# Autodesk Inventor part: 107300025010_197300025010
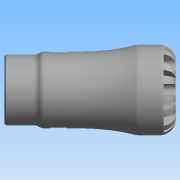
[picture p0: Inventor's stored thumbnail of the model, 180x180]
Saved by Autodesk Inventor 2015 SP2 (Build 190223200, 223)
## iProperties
Created: 2016-12
Part Number: 107300025010_197300025010
Material: Generic
Description: PLASSON FEMALE INTEGRAL BRASS THREAD 25X1" SERIES 1
Document SubType Name: Modeling
Designer: KIM
Density: 1 g/cm^3
Appearance: Default
Author: KIM
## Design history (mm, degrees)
derived "1073.ipt"
feature "Solid1::1073.ipt"
tag "TaggingFeature1"
body "Solid1"
other parameters: "d0" = 89, "d1" = 20.16, "d2" = 25, "d3" = 31.25, "d4" = 47, "d6" = 48, "d8" = 39.95, "d13" = 6.3, "d14" = 6.3, "d15" = 0, "d17" = 360 deg, "d19" = 8 deg, "d20" = 0.5, "d21" = 0.5, "d22" = 8 deg, "d24" = 0, "d26" = 360 deg, "d32" = 4.7, "d33" = 4.7, "d39" = 0.90873, "d42" = 30.291, "d43" = 36.66, "d46" = 2.08333, "d47" = 19, "d48" = 28.77645, "d50" = 7.26, "d51" = 0.47, "d54" = 8.75, "d55" = 5.5, "d57" = 12.348, "d58" = 0, "d68" = 360 deg, "d72" = 0.5, "d74" = 0, "d76" = 7.4375, "d_" = 25, "E_" = 47, "H_" = 89, "l_" = 48, "G_" = 30.291, "l_2" = 19, "d9" = 7.875, "d11" = 47, "d12" = 31.25, "d49" = 22
